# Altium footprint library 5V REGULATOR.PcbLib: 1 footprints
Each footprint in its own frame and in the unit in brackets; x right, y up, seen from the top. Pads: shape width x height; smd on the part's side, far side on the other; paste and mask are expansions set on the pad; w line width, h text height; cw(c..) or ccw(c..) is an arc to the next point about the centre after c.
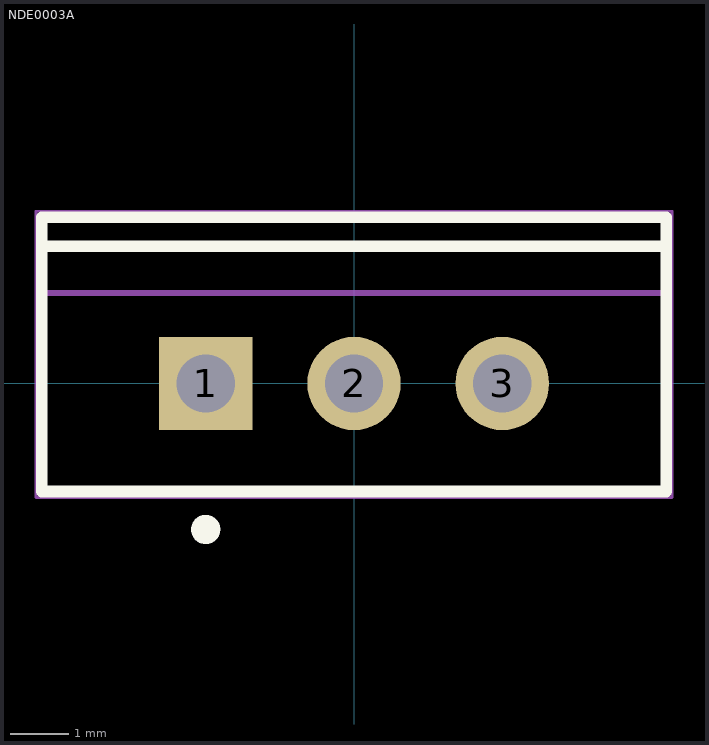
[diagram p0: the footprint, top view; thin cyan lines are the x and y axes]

## NDE0003A [mm] "FM, 3-Leads, Body 10.7x4.7mm, Pitch 2.54mm"
height 19.4
pads (3):
  rect 1.6x1.6 hole 1: 1(-2.54,0)
  round 1.6 hole 1: 2(0,0) 3(2.54,0)
Top Overlay:
  circle w0.25: c-2.54,-2.5 r0.125
  lines w0.2: -5.35,2.35 5.35,2.35 ; -5.35,-1.85 5.35,-1.85 5.35,2.85 -5.35,2.85 -5.35,-1.85
Mechanical 1:
  text ".Designator" at -1.524,-0.508 h1.02
Mechanical 13:
  lines w0.1: -5.35,1.55 5.35,1.55 ; -5.35,-1.85 5.35,-1.85 5.35,2.85 -5.35,2.85 -5.35,-1.85
Mechanical 15:
  lines w0.05: -5.45,-1.95 -5.45,2.95 5.45,2.95 5.45,-1.95 -5.45,-1.95
  lines w0.1: -0.5,0 0.5,0 ; 0,-0.5 0,0.5
3D body: height 19.4, standoff 12.9, extent -5.349,1.551 5.349,2.849
3D body: height 12.9, standoff 4, extent -5.4,-1.9 5.4,2.9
